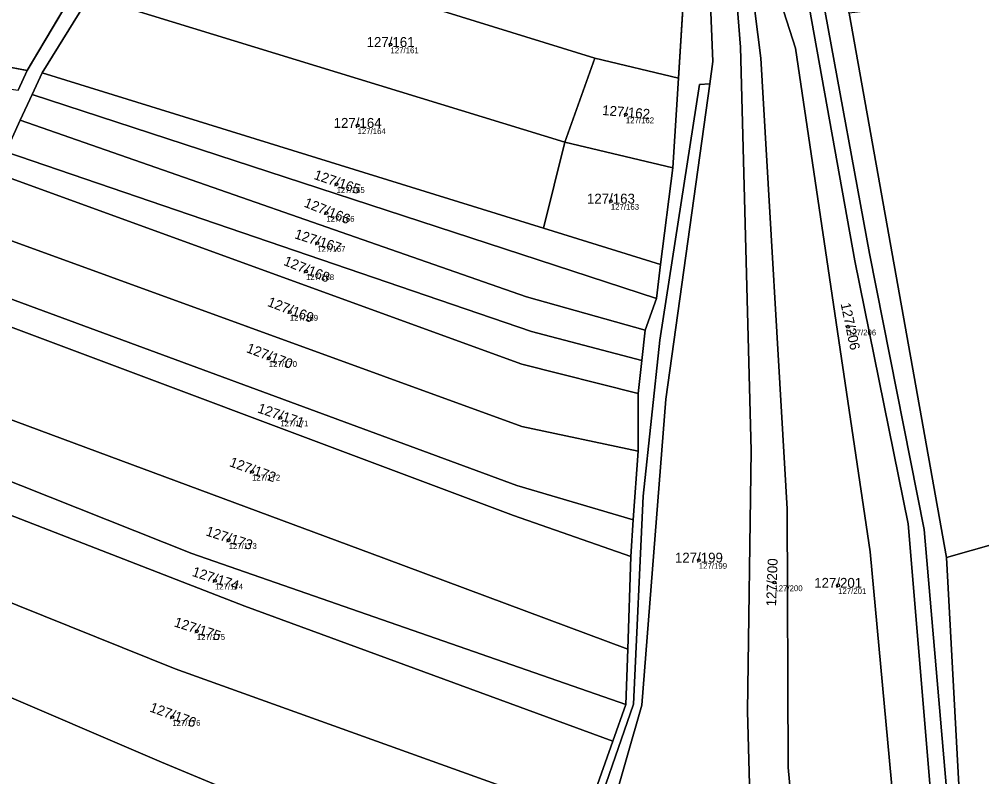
# Model space of a CAD drawing. Extents: x -603967 to -594699, y -1179315 to -1165625.
# Drawn here: x -597499.3 to -597334.3, y -1173222.3 to -1173092.5 of the extents above; entities that cross this region are included whole.
import ezdxf

# ---------------------------------------------------------------- set-up
doc = ezdxf.new("R2010")
doc.units = 0
for name, color, linetype in [('Definiční body', 7, 'Continuous'), ('Hranice parcel', 7, 'Continuous'), ('Parcelní čísla', 7, 'Continuous'), ('Polygon parcely', 7, 'Continuous')]:
    doc.layers.add(name, color=color, linetype=linetype)

msp = doc.modelspace()

# ---------------------------------------------------------------- linework, layer by layer
at = {"layer": 'Definiční body'}
for centre in [(-597435.66, -1173096.82994), (-597395.32, -1173108.82994), (-597441.31, -1173110.68994), (-597444.91, -1173120.76994), (-597397.89, -1173123.65994), (-597446.66, -1173125.70994), (-597448.21, -1173130.85994), (-597450.16, -1173135.69994), (-597452.91, -1173142.65994), (-597357.25, -1173145.17994), (-597456.52, -1173150.57994), (-597454.56, -1173160.76994), (-597459.4, -1173170.03994), (-597463.41, -1173181.76994), (-597382.81, -1173185.16994), (-597465.76, -1173188.70994), (-597369.86, -1173188.99994), (-597358.94, -1173189.48994), (-597468.85, -1173197.34994), (-597473.07, -1173212.06994)]:
    msp.add_circle(centre, 0.25, dxfattribs=at)
at = {"layer": 'Hranice parcel'}
for p, q in [((-597478.79, -1173074.94), (-597400.65, -1173099.16)), ((-597386.3, -1173102.61), (-597385.13, -1173084.35)), ((-597497.91, -1173101.27), (-597490.13, -1173088.07)), ((-597487.23, -1173088.56), (-597495.37, -1173101.69)), ((-597487.23, -1173088.56), (-597405.79, -1173113.57)), ((-597357.02, -1173091.48), (-597340.37, -1173184.71)), ((-597497.91, -1173101.27), (-597539.59, -1173093.53)), ((-597405.79, -1173113.57), (-597400.65, -1173099.16)), ((-597400.65, -1173099.16), (-597386.3, -1173102.61)), ((-597499.48, -1173104.67), (-597497.91, -1173101.27)), ((-597495.37, -1173101.69), (-597497.07, -1173105.4)), ((-597495.37, -1173101.69), (-597409.43, -1173128.3)), ((-597387.26, -1173117.98), (-597386.3, -1173102.61)), ((-597497.07, -1173105.4), (-597499.11, -1173109.82)), ((-597497.07, -1173105.4), (-597390.08, -1173140.35)), ((-597499.11, -1173109.82), (-597501.58, -1173115.24)), ((-597405.79, -1173113.57), (-597409.43, -1173128.3)), ((-597405.79, -1173113.57), (-597387.26, -1173117.98)), ((-597389.39, -1173134.51), (-597387.26, -1173117.98)), ((-597409.43, -1173128.3), (-597389.39, -1173134.51)), ((-597390.08, -1173140.35), (-597389.39, -1173134.51)), ((-597392, -1173145.76), (-597390.08, -1173140.35)), ((-597392.58, -1173150.97), (-597392, -1173145.76)), ((-597393.21, -1173156.65), (-597392.58, -1173150.97)), ((-597393.22, -1173166.52), (-597393.21, -1173156.65)), ((-597394.05, -1173178.28), (-597393.22, -1173166.52)), ((-597340.37, -1173184.71), (-597299.69, -1173173.18)), ((-597394.47, -1173184.52), (-597394.05, -1173178.28)), ((-597395, -1173200.4), (-597394.47, -1173184.52)), ((-597395.32, -1173209.93), (-597395, -1173200.4)), ((-597397.53, -1173216.17), (-597395.32, -1173209.93)), ((-597402.11, -1173229.07), (-597397.53, -1173216.17))]:
    msp.add_line(p, q, dxfattribs=at)
for points in [[(-597341.88, -1173256.44), (-597340.26, -1173250.03), (-597339.32, -1173236.26), (-597344.17, -1173179.9), (-597353.54, -1173132.63), (-597361.17, -1173091.31), (-597366.08, -1173066.31), (-597374.64, -1173050.36), (-597380.37, -1173039.62), (-597387.47, -1173019.8), (-597399.32, -1172964.53), (-597404.92, -1172923.92), (-597423.04, -1172835.13), (-597437.05, -1172782.74)], [(-597385.23, -1173035.74), (-597369.64, -1173064.26), (-597366.45, -1173075.97), (-597356.05, -1173133.92), (-597346.95, -1173178.93), (-597342.27, -1173235.11), (-597342.62, -1173248.49), (-597344.24, -1173255.93)], [(-597378.77, -1173058.37), (-597382.07, -1173058.99), (-597380.42, -1173099.75), (-597380.95, -1173103.54)], [(-597373.26, -1173254.96), (-597374.47, -1173211.02), (-597373.85, -1173166.41), (-597375.69, -1173097.31), (-597378.77, -1173058.37)], [(-597364.3, -1173255.1), (-597367.48, -1173220.7), (-597367.67, -1173176.36), (-597372.2, -1173099.16), (-597376.39, -1173065.79)], [(-597346.84, -1173255.37), (-597353.46, -1173183.74), (-597366.22, -1173097.48), (-597376.39, -1173065.79)], [(-597380.95, -1173103.54), (-597382.69, -1173103.69), (-597389.48, -1173147.51), (-597392.36, -1173174.23), (-597394.01, -1173209.84), (-597409.64, -1173255.1), (-597411.9, -1173296.2), (-597410.66, -1173315.96), (-597400.29, -1173377.25)], [(-597380.95, -1173103.54), (-597388.45, -1173157.59), (-597392.56, -1173210), (-597405.32, -1173254.45)], [(-597499.11, -1173109.82), (-597412.33, -1173140.05), (-597392, -1173145.76)], [(-597501.58, -1173115.24), (-597411.51, -1173146.02), (-597392.58, -1173150.97)], [(-597503.24, -1173118.85), (-597413.15, -1173151.58), (-597393.21, -1173156.65)], [(-597507.45, -1173128.03), (-597413.15, -1173162.29), (-597393.22, -1173166.52)], [(-597511.35, -1173136.53), (-597413.98, -1173172.37), (-597394.05, -1173178.28)], [(-597513.22, -1173140.6), (-597414.59, -1173177.52), (-597394.47, -1173184.52)], [(-597519.45, -1173154.19), (-597436.78, -1173184.85), (-597395, -1173200.4)], [(-597523.36, -1173162.71), (-597469.7, -1173184.02), (-597395.32, -1173209.93)], [(-597525.71, -1173167.84), (-597460.65, -1173193.08), (-597397.53, -1173216.17)], [(-597531.27, -1173180.19), (-597472.58, -1173203.79), (-597402.11, -1173229.07)], [(-597340.37, -1173184.71), (-597337.35, -1173240.49), (-597336.82, -1173257.52)], [(-597535.59, -1173193.78), (-597474.9, -1173219.8), (-597408.96, -1173247.24)]]:
    msp.add_lwpolyline(points, dxfattribs=at)
at = {"layer": 'Polygon parcely'}
for points in [[(-597401.86, -1172966.79), (-597391.47, -1173016.9), (-597386.2, -1173032.57), (-597385.23, -1173035.74), (-597369.64, -1173064.26), (-597366.45, -1173075.97), (-597356.05, -1173133.92), (-597346.95, -1173178.93), (-597342.27, -1173235.11), (-597342.62, -1173248.49), (-597344.24, -1173255.93), (-597343.63, -1173256.06), (-597341.88, -1173256.44), (-597340.26, -1173250.03), (-597339.32, -1173236.26), (-597344.17, -1173179.9), (-597353.54, -1173132.63), (-597361.17, -1173091.31), (-597366.08, -1173066.31), (-597374.64, -1173050.36), (-597380.37, -1173039.62), (-597387.47, -1173019.8), (-597399.32, -1172964.53)], [(-597399.32, -1172964.53), (-597387.47, -1173019.8), (-597380.37, -1173039.62), (-597374.64, -1173050.36), (-597366.08, -1173066.31), (-597361.17, -1173091.31), (-597353.54, -1173132.63), (-597344.17, -1173179.9), (-597339.32, -1173236.26), (-597340.26, -1173250.03), (-597341.88, -1173256.44), (-597340.86, -1173256.64), (-597336.82, -1173257.52), (-597337.35, -1173240.49), (-597340.37, -1173184.71), (-597357.02, -1173091.48), (-597366.96, -1173054.01), (-597384.66, -1173008.07)], [(-597501.58, -1173115.24), (-597499.11, -1173109.82), (-597497.07, -1173105.4), (-597495.37, -1173101.69), (-597487.23, -1173088.56), (-597478.79, -1173074.94), (-597469.4, -1173062.07), (-597457.59, -1173048.75), (-597451.97, -1173043.58), (-597443.88, -1173036.25), (-597440.58, -1173033.27), (-597436.6, -1173030.78), (-597434.44, -1173029.43), (-597441.05, -1173028.58), (-597447.67, -1173034.68), (-597456.17, -1173042.53), (-597460.93, -1173047.08), (-597472.89, -1173062), (-597482.04, -1173074.48), (-597490.13, -1173088.07), (-597497.91, -1173101.27), (-597499.48, -1173104.67)], [(-597409.64, -1173255.1), (-597394.01, -1173209.84), (-597392.36, -1173174.23), (-597389.48, -1173147.51), (-597382.69, -1173103.69), (-597380.95, -1173103.54), (-597380.42, -1173099.75), (-597382.07, -1173058.99)], [(-597385.13, -1173084.35), (-597386.3, -1173102.61), (-597387.26, -1173117.98), (-597389.39, -1173134.51), (-597390.08, -1173140.35), (-597392, -1173145.76), (-597392.58, -1173150.97), (-597393.21, -1173156.65), (-597393.22, -1173166.52), (-597394.05, -1173178.28), (-597394.47, -1173184.52), (-597395, -1173200.4), (-597395.32, -1173209.93), (-597397.53, -1173216.17), (-597402.11, -1173229.07)]]:
    msp.add_lwpolyline(points, dxfattribs=at)
for points in [[(-597388.35, -1173035.34), (-597378.77, -1173058.37), (-597376.39, -1173065.79), (-597366.22, -1173097.48), (-597353.46, -1173183.74), (-597346.84, -1173255.37), (-597344.24, -1173255.93), (-597342.62, -1173248.49), (-597342.27, -1173235.11), (-597346.95, -1173178.93), (-597356.05, -1173133.92), (-597366.45, -1173075.97), (-597369.64, -1173064.26), (-597385.23, -1173035.74)], [(-597375.69, -1173097.31), (-597378.77, -1173058.37), (-597382.07, -1173058.99), (-597380.42, -1173099.75), (-597380.95, -1173103.54), (-597388.45, -1173157.59), (-597392.56, -1173210), (-597405.32, -1173254.45), (-597380.77, -1173254.84), (-597373.26, -1173254.96), (-597374.47, -1173211.02), (-597373.85, -1173166.41)], [(-597367.48, -1173220.7), (-597367.67, -1173176.36), (-597372.2, -1173099.16), (-597376.39, -1173065.79), (-597378.77, -1173058.37), (-597375.69, -1173097.31), (-597373.85, -1173166.41), (-597374.47, -1173211.02), (-597373.26, -1173254.96), (-597372.02, -1173254.98), (-597364.3, -1173255.1)], [(-597478.79, -1173074.94), (-597400.65, -1173099.16), (-597386.3, -1173102.61), (-597385.13, -1173084.35), (-597469.4, -1173062.07)], [(-597366.22, -1173097.48), (-597376.39, -1173065.79), (-597372.2, -1173099.16), (-597367.67, -1173176.36), (-597367.48, -1173220.7), (-597364.3, -1173255.1), (-597346.84, -1173255.37), (-597353.46, -1173183.74)], [(-597487.23, -1173088.56), (-597405.79, -1173113.57), (-597400.65, -1173099.16), (-597478.79, -1173074.94)], [(-597497.91, -1173101.27), (-597490.13, -1173088.07), (-597537.26, -1173079.97), (-597539.59, -1173093.53)], [(-597299.69, -1173173.18), (-597309.04, -1173085.62), (-597357.02, -1173091.48), (-597340.37, -1173184.71)], [(-597409.43, -1173128.3), (-597405.79, -1173113.57), (-597487.23, -1173088.56), (-597495.37, -1173101.69)], [(-597499.48, -1173104.67), (-597497.91, -1173101.27), (-597539.59, -1173093.53), (-597540.46, -1173098.59)], [(-597387.26, -1173117.98), (-597386.3, -1173102.61), (-597400.65, -1173099.16), (-597405.79, -1173113.57)], [(-597497.07, -1173105.4), (-597390.08, -1173140.35), (-597389.39, -1173134.51), (-597409.43, -1173128.3), (-597495.37, -1173101.69)], [(-597394.01, -1173209.84), (-597409.64, -1173255.1), (-597411.9, -1173296.2), (-597410.66, -1173315.96), (-597400.29, -1173377.25), (-597398.08, -1173375.21), (-597406.11, -1173313.63), (-597405.32, -1173254.45), (-597392.56, -1173210), (-597388.45, -1173157.59), (-597380.95, -1173103.54), (-597382.69, -1173103.69), (-597389.48, -1173147.51), (-597392.36, -1173174.23)], [(-597392, -1173145.76), (-597390.08, -1173140.35), (-597497.07, -1173105.4), (-597499.11, -1173109.82), (-597412.33, -1173140.05)], [(-597392.58, -1173150.97), (-597392, -1173145.76), (-597412.33, -1173140.05), (-597499.11, -1173109.82), (-597501.58, -1173115.24), (-597411.51, -1173146.02)], [(-597409.43, -1173128.3), (-597389.39, -1173134.51), (-597387.26, -1173117.98), (-597405.79, -1173113.57)], [(-597393.21, -1173156.65), (-597392.58, -1173150.97), (-597411.51, -1173146.02), (-597501.58, -1173115.24), (-597503.24, -1173118.85), (-597413.15, -1173151.58)], [(-597393.22, -1173166.52), (-597393.21, -1173156.65), (-597413.15, -1173151.58), (-597503.24, -1173118.85), (-597507.45, -1173128.03), (-597413.15, -1173162.29)], [(-597413.98, -1173172.37), (-597394.05, -1173178.28), (-597393.22, -1173166.52), (-597413.15, -1173162.29), (-597507.45, -1173128.03), (-597511.35, -1173136.53)], [(-597414.59, -1173177.52), (-597394.47, -1173184.52), (-597394.05, -1173178.28), (-597413.98, -1173172.37), (-597511.35, -1173136.53), (-597513.22, -1173140.6)], [(-597436.78, -1173184.85), (-597395, -1173200.4), (-597394.47, -1173184.52), (-597414.59, -1173177.52), (-597513.22, -1173140.6), (-597519.45, -1173154.19)], [(-597395.32, -1173209.93), (-597395, -1173200.4), (-597436.78, -1173184.85), (-597519.45, -1173154.19), (-597523.36, -1173162.71), (-597469.7, -1173184.02)], [(-597397.53, -1173216.17), (-597395.32, -1173209.93), (-597469.7, -1173184.02), (-597523.36, -1173162.71), (-597525.71, -1173167.84), (-597460.65, -1173193.08)], [(-597402.11, -1173229.07), (-597397.53, -1173216.17), (-597460.65, -1173193.08), (-597525.71, -1173167.84), (-597531.27, -1173180.19), (-597472.58, -1173203.79)], [(-597167.37, -1173173.96), (-597172.05, -1173173.96), (-597173.32, -1173182.18), (-597260.83, -1173182.27), (-597260.84, -1173174.27), (-597271.15, -1173169.07), (-597287.52, -1173170.77), (-597299.69, -1173173.18), (-597340.37, -1173184.71), (-597337.35, -1173240.49), (-597336.82, -1173257.52), (-597302.53, -1173264.95), (-597273.37, -1173276.16), (-597235.54, -1173279.29), (-597203.06, -1173285.97)], [(-597408.96, -1173247.24), (-597402.11, -1173229.07), (-597472.58, -1173203.79), (-597531.27, -1173180.19), (-597535.59, -1173193.78), (-597474.9, -1173219.8)], [(-597539.27, -1173207.67), (-597474.86, -1173236.29), (-597414.15, -1173260.99), (-597408.96, -1173247.24), (-597474.9, -1173219.8), (-597535.59, -1173193.78)]]:
    msp.add_lwpolyline(points, close=True, dxfattribs=at)

# ---------------------------------------------------------------- texts
at = {"layer": 'Definiční body'}
for s, p in [('127/161', (-597435.66, -1173098.319)), ('127/162', (-597395.32, -1173110.319)), ('127/164', (-597441.31, -1173112.179)), ('127/165', (-597444.91, -1173122.259)), ('127/163', (-597397.89, -1173125.149)), ('127/166', (-597446.66, -1173127.199)), ('127/167', (-597448.21, -1173132.349)), ('127/168', (-597450.16, -1173137.189)), ('127/169', (-597452.91, -1173144.149)), ('127/206', (-597357.25, -1173146.669)), ('127/170', (-597456.52, -1173152.069)), ('127/171', (-597454.56, -1173162.259)), ('127/172', (-597459.4, -1173171.529)), ('127/173', (-597463.41, -1173183.259)), ('127/199', (-597382.81, -1173186.659)), ('127/174', (-597465.76, -1173190.199)), ('127/200', (-597369.86, -1173190.489)), ('127/201', (-597358.94, -1173190.979)), ('127/175', (-597468.85, -1173198.839)), ('127/176', (-597473.07, -1173213.559))]:
    msp.add_text(s, height=0.999996, dxfattribs=at).set_placement(p)
at = {"layer": 'Parcelní čísla'}
for s, p in [('127/161', (-597439.756, -1173097.255)), ('127/164', (-597445.406, -1173111.115)), ('127/163', (-597401.986, -1173124.085)), ('127/199', (-597386.906, -1173185.595)), ('127/201', (-597363.036, -1173189.915))]:
    msp.add_text(s, height=1.699998, dxfattribs=at).set_placement(p)
for s, rotation, p in [('127/162', 355, (-597399.438, -1173108.896)), ('127/165', 340.9999972, (-597448.921, -1173119.838)), ('127/166', 338, (-597450.617, -1173124.569)), ('127/167', 342, (-597452.237, -1173129.998)), ('127/168', 338, (-597454.117, -1173134.559)), ('127/169', 339, (-597456.886, -1173141.588)), ('127/206', 282, (-597358.517, -1173141.261)), ('127/170', 339, (-597460.496, -1173149.508)), ('127/171', 340.9999972, (-597458.571, -1173159.838)), ('127/172', 340, (-597463.395, -1173169.038)), ('127/173', 342, (-597467.437, -1173180.908)), ('127/200', 87.9999972, (-597369.578, -1173193.109)), ('127/174', 342, (-597469.787, -1173187.848)), ('127/175', 342, (-597472.877, -1173196.488)), ('127/176', 340, (-597477.065, -1173211.068))]:
    msp.add_text(s, height=1.699998, rotation=rotation, dxfattribs=at).set_placement(p)

doc.saveas('drawing.dxf')
